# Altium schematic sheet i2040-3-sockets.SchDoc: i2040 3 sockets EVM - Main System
size 431 x 279 mm; VersionControl_RevNumber: 1; Date: Not shown in title block; ApprovedBy: Not shown in title block; CheckedBy: Not shown in title block; Author: Not shown in title block; CompanyName: Texas Instruments; DrawnBy: Mars Leung; Engineer: Mars Leung; Organization: Smartgrid Hong Kong; Address1: Not shown in title block; Address2: Not shown in title block; Address3: Not shown in title block; Address4: Not shown in title block; DocumentNumber: 1; Revision: Use project parameter SCH_Rev; SheetNumber: 1; SheetTotal: 3; PageSetup: Record=PageOptions|CenterHorizontal=True|CenterVertical=True|PrintScale=0.62|XCorrection=1.00|YCorrection=1.00|PrintKind=0|BorderSize=5000000|LeftOffset=0|BottomOffset=0|Orientation=2|PaperLength=1000|PaperWidth=1000|Scale=100|PaperSource=15|PrintQuality=600|MediaType=1|DitherType=10|PaperKind=Letter|PrintScaleMode=1
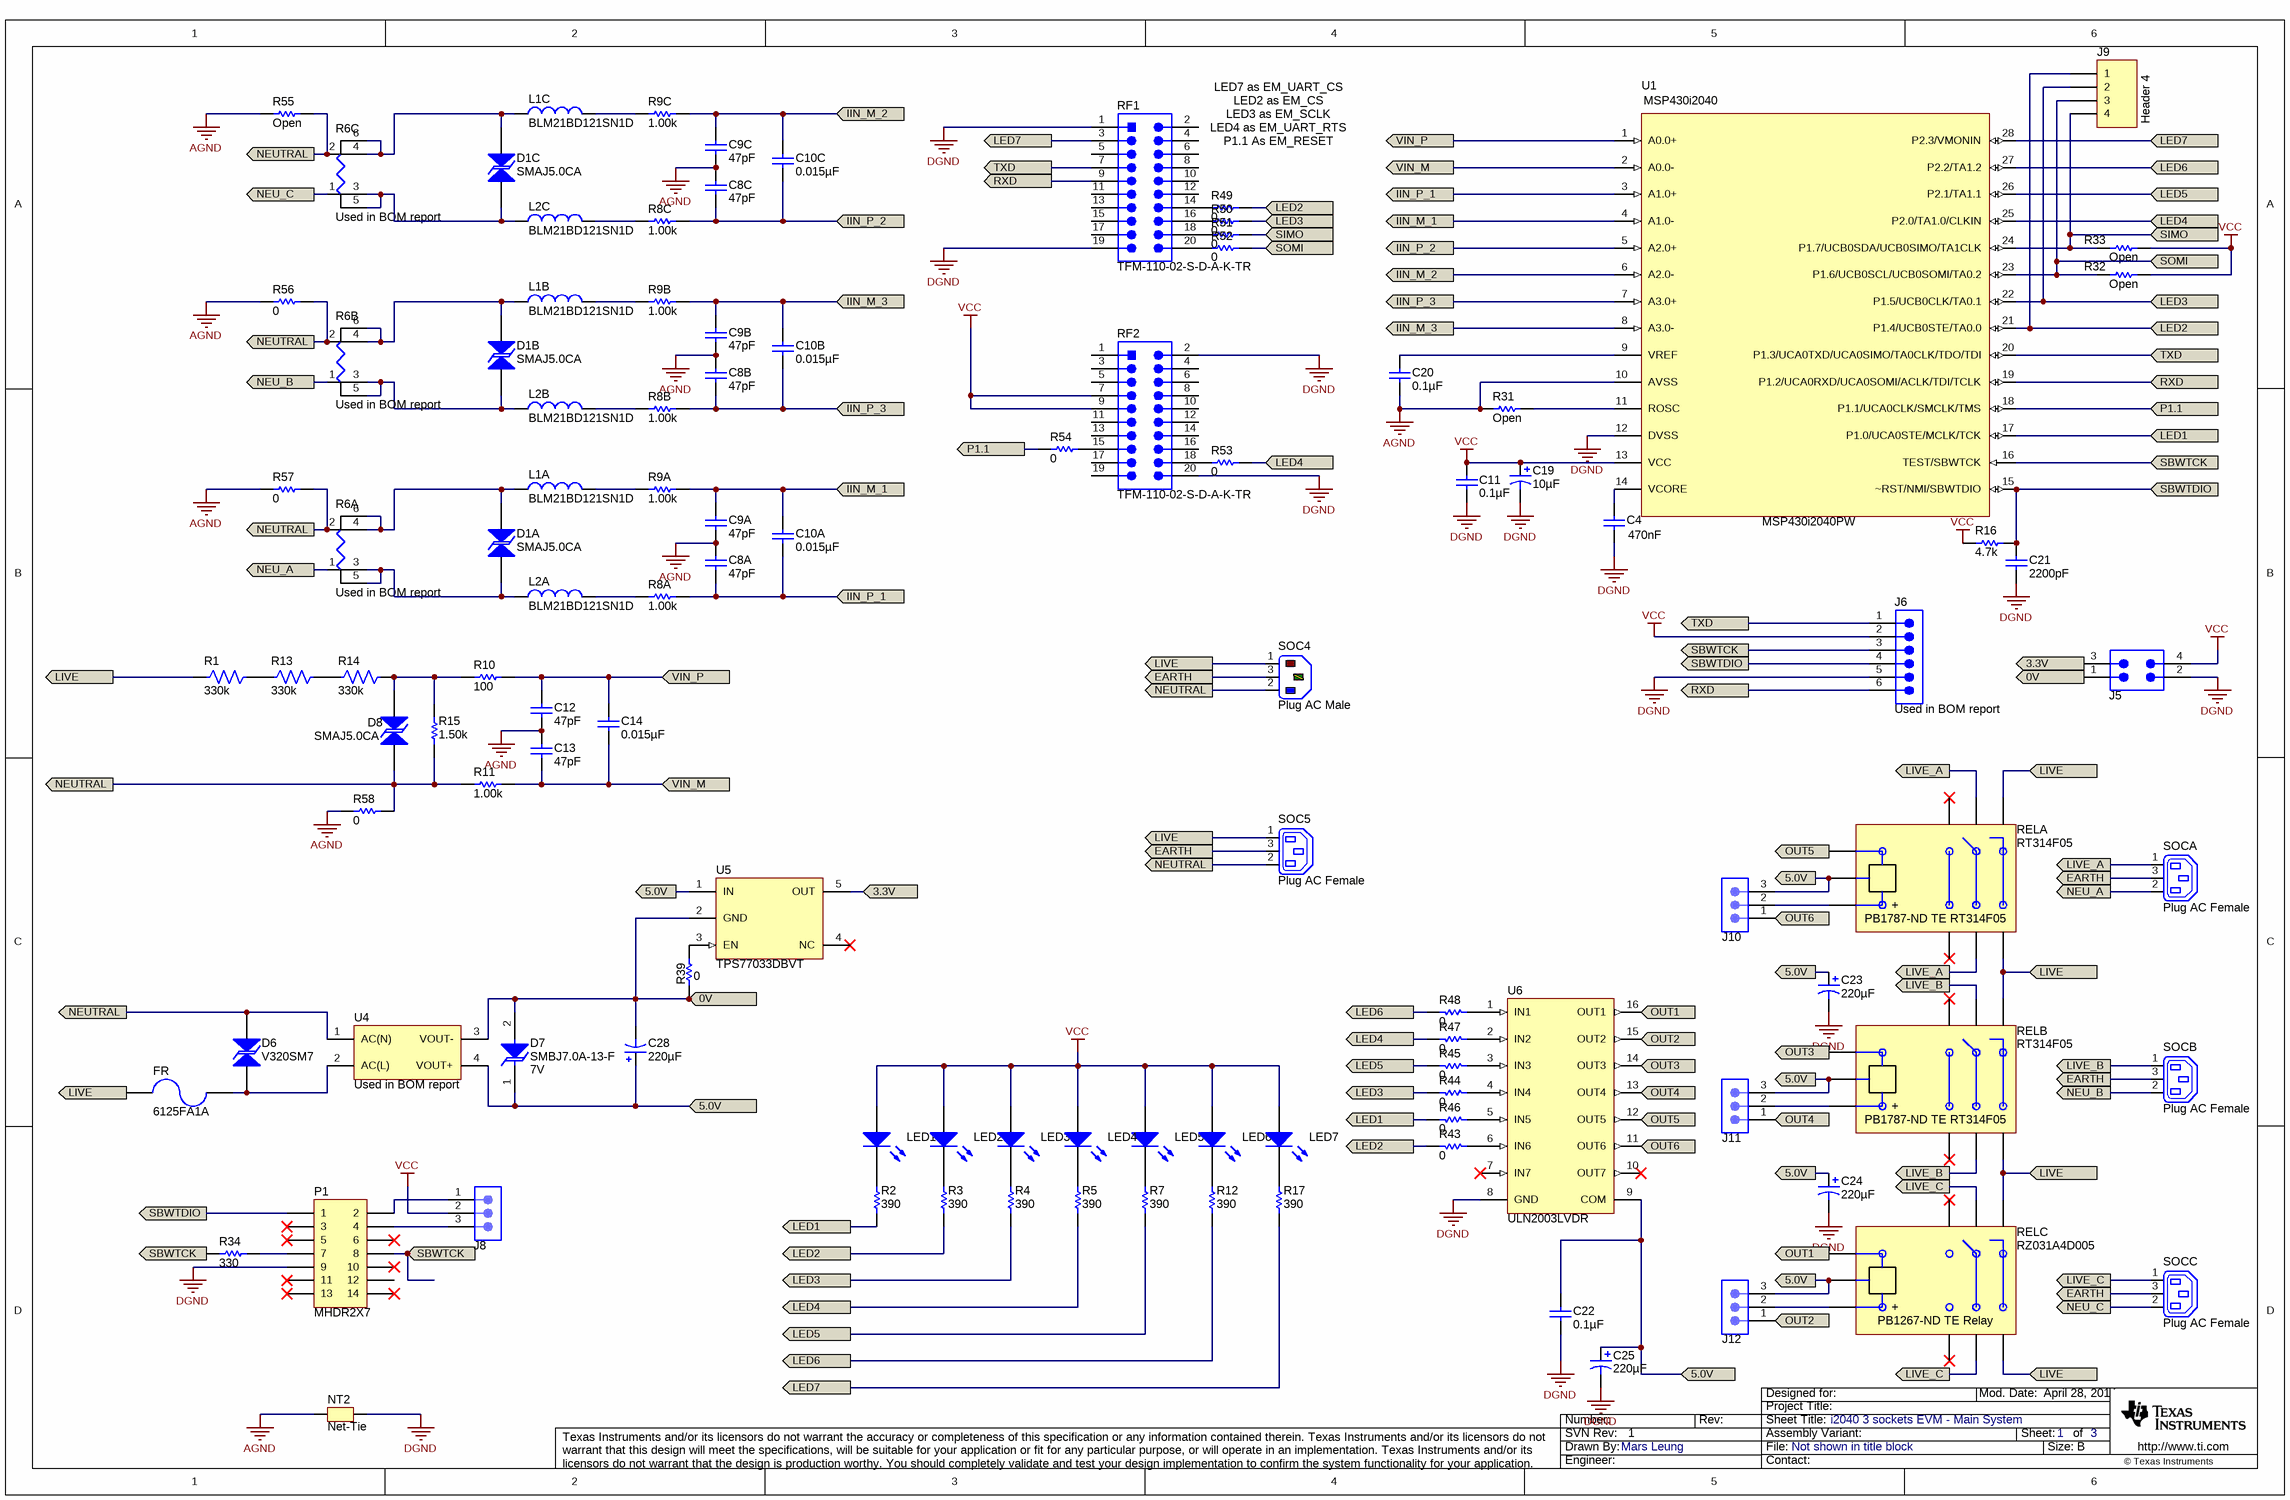
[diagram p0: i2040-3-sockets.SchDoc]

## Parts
C4  470nF  [0603]
C8A  ValueDisplayed: 47pF  [0603]  (hidden comment: 06035A470JAT2A)
C8B  ValueDisplayed: 47pF  [0603]  (hidden comment: 06035A470JAT2A)
C8C  ValueDisplayed: 47pF  [0603]  (hidden comment: 06035A470JAT2A)
C9A  ValueDisplayed: 47pF  [0603]  (hidden comment: 06035A470JAT2A)
C9B  ValueDisplayed: 47pF  [0603]  (hidden comment: 06035A470JAT2A)
C9C  ValueDisplayed: 47pF  [0603]  (hidden comment: 06035A470JAT2A)
C10A  ValueDisplayed: 0.015µF  [0603]  (hidden comment: GRM188R71C153KA01D)
C10B  ValueDisplayed: 0.015µF  [0603]  (hidden comment: GRM188R71C153KA01D)
C10C  ValueDisplayed: 0.015µF  [0603]  (hidden comment: GRM188R71C153KA01D)
C11  ValueDisplayed: 0.1µF  [0402]  (hidden comment: 0.1uF)
C12  ValueDisplayed: 47pF  [0603]  (hidden comment: 06035A470JAT2A)
C13  ValueDisplayed: 47pF  [0603]  (hidden comment: 06035A470JAT2A)
C14  ValueDisplayed: 0.015µF  [0603]  (hidden comment: GRM188R71C153KA01D)
C19  ValueDisplayed: 10µF  [3528-21]  (hidden comment: 293D106X0010B2TE3)
C20  ValueDisplayed: 0.1µF  [0402]  (hidden comment: 0.1uF)
C21  ValueDisplayed: 2200pF  [0603]  (hidden comment: C0603X222K5RACTU)
C22  ValueDisplayed: 0.1µF  [0402]  (hidden comment: 0.1uF)
C23  ValueDisplayed: 220µF  [7343-31]  (hidden comment: 293D227X96R3D2TE3)
C24  ValueDisplayed: 220µF  [7343-31]  (hidden comment: 293D227X96R3D2TE3)
C25  ValueDisplayed: 220µF  [7343-31]  (hidden comment: 293D227X96R3D2TE3)
C28  ValueDisplayed: 220µF  [7343-31]  (hidden comment: 293D227X96R3D2TE3)
D1A  SMAJ5.0CA  [DSO-C2/X1.8]
D1B  SMAJ5.0CA  [DSO-C2/X1.8]
D1C  SMAJ5.0CA  [DSO-C2/X1.8]
D6  V320SM7  [V320SM7]
D7  SMBJ7.0A-13-F  value 7V  [SMB]
D8  SMAJ5.0CA  [DSO-C2/X1.8]
FR  6125FA1A  [6125FA]
J5  TSW-102-07-G-D  [TSW-102-07-G-D]  (value not drawn)
J6  Used in BOM report  [6-pin header (1.27mm)]
J8  PBC03SAAN  [PBC03SAAN]  (value not drawn)
J9  Header 4  [HDR1X4]
J10  PBC03SAAN  [PBC03SAAN]  (value not drawn)
J11  PBC03SAAN  [PBC03SAAN]  (value not drawn)
J12  PBC03SAAN  [PBC03SAAN]  (value not drawn)
L1A  BLM21BD121SN1D  [YW0805]
L1B  BLM21BD121SN1D  [YW0805]
L1C  BLM21BD121SN1D  [YW0805]
L2A  BLM21BD121SN1D  [YW0805]
L2B  BLM21BD121SN1D  [YW0805]
L2C  BLM21BD121SN1D  [YW0805]
LED1  Used in BOM report  [0805-LED]  (value not drawn)
LED2  Used in BOM report  [0805-LED]  (value not drawn)
LED3  Used in BOM report  [0805-LED]  (value not drawn)
LED4  Used in BOM report  [0805-LED]  (value not drawn)
LED5  Used in BOM report  [0805-LED]  (value not drawn)
LED6  Used in BOM report  [0805-LED]  (value not drawn)
LED7  Used in BOM report  [0805-LED]  (value not drawn)
NT2  Net-Tie  [Net-Tie_10mil]  (net tie, no BOM)
P1  MHDR2X7  [2X7BOXHEADER]
R1  330k  [R2512]
R2  390  [0603]
R3  390  [0603]
R4  390  [0603]
R5  390  [0603]
R6A  Used in BOM report  [Current Sensing Pad]
R6B  Used in BOM report  [Current Sensing Pad]
R6C  Used in BOM report  [Current Sensing Pad]
R7  390  [0603]
R8A  1.00k  [0603]
R8B  1.00k  [0603]
R8C  1.00k  [0603]
R9A  1.00k  [0603]
R9B  1.00k  [0603]
R9C  1.00k  [0603]
R10  100  [0603]
R11  1.00k  [0603]
R12  390  [0603]
R13  330k  [R2512]
R14  330k  [R2512]
R15  1.50k  [0805]
R16  4.7k  [0603]
R17  390  [0603]
R31  Open  [0603]
R32  Open  [0603]
R33  Open  [0603]
R34  330  [0603]
R39  0  [0603]
R43  0  [0603]
R44  0  [0603]
R45  0  [0603]
R46  0  [0603]
R47  0  [0603]
R48  0  [0603]
R49  0  [0603]
R50  0  [0603]
R51  0  [0603]
R52  0  [0603]
R53  0  [0603]
R54  0  [0603]
R55  value Open  [0805_HV]  (hidden comment: CRCW08050000Z0EA)
R56  value 0  [0805_HV]  (hidden comment: CRCW08050000Z0EA)
R57  value 0  [0805_HV]  (hidden comment: CRCW08050000Z0EA)
R58  value 0  [0805_HV]  (hidden comment: CRCW08050000Z0EA)
RELA  RT314F05  [TE RELAY TYPE A]
RELB  RT314F05  [TE RELAY TYPE A]
RELC  RZ031A4D005  [TE RELAY TYPE A]
RF1  TFM-110-02-S-D-A-K-TR  [Samtec_TFM-110-02-S-D-A-K]
RF2  TFM-110-02-S-D-A-K-TR  [Samtec_TFM-110-02-S-D-A-K]
SOC4  Plug AC Male  [IEC9.14-2H3]
SOC5  Plug AC Female  [IEC7-2H3]
SOCA  Plug AC Female  [IEC7-2H3]
SOCB  Plug AC Female  [IEC7-2H3]
SOCC  Plug AC Female  [IEC7-2H3]
U1  MSP430i2040PW  [TSSO10x6-G28]
U4  Used in BOM report  [VSK-S1]
U5  TPS77033DBVT  [DBV0005A_N]
U6  ULN2003LVDR  [D0016A_N]

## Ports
0V, 3.3V, 5.0V, EARTH, IIN_M_1, IIN_M_2, IIN_M_3, IIN_P_1, IIN_P_2, IIN_P_3, LED1, LED2, LED3, LED4, LED5, LED6, LED7, LIVE, LIVE_A, LIVE_B, LIVE_C, NEU_A, NEU_B, NEU_C, NEUTRAL, OUT1, OUT2, OUT3, OUT4, OUT5, OUT6, P1.1, RXD, SBWTCK, SBWTDIO, SIMO, SOMI, TXD, VIN_M, VIN_P

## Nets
AGND: C8A.1 C8B.1 C8C.1 C9A.2 C9B.2 C9C.2 C12.2 C13.1 C20.2 NT2.1 R31.1 R55.1 R56.1 R57.1 R58.1 U1.10(AVSS)
DGND: C4.2 C11.2 C19.2(-) C21.2 C22.2 C23.2(-) C24.2(-) C25.2(-) J5.2 J6.5 NT2.2 P1.9 RF1.1 RF1.19 RF2.2 RF2.20 U1.12(DVSS) U6.8(GND)
VCC: C11.1 C19.1(+) J5.4 J6.2 J8.2 LED1.1(A) LED2.1(A) LED3.1(A) LED4.1(A) LED5.1(A) LED6.1(A) LED7.1(A) R16.1 R32.2 R33.2 RF2.7 RF2.9 U1.13(VCC)
0V: C28.2(-) D7.2(A) J5.1 R39.2 U4.3(VOUT-) U5.2(GND) ; port 0V
3.3V: J5.3 U5.5(OUT) ; port 3.3V
5.0V: C22.1 C23.1(+) C24.1(+) C25.1(+) C28.1(+) D7.1(K) J10.3 J11.3 J12.3 RELA.9 RELB.9 RELC.9 U4.4(VOUT+) U5.1(IN) U6.9(COM) ; port 5.0V
EARTH: SOC4.3(E) SOC5.3(E) SOCA.3(E) SOCB.3(E) SOCC.3(E) ; port EARTH
IIN_M_1: C9A.1 C10A.1 R9A.2 U1.4(A1.0-) ; port IIN_M_1
IIN_M_2: C9C.1 C10C.1 R9C.2 U1.6(A2.0-) ; port IIN_M_2
IIN_M_3: C9B.1 C10B.1 R9B.2 U1.8(A3.0-) ; port IIN_M_3
IIN_P_1: C8A.2 C10A.2 R8A.2 U1.3(A1.0+) ; port IIN_P_1
IIN_P_2: C8C.2 C10C.2 R8C.2 U1.5(A2.0+) ; port IIN_P_2
IIN_P_3: C8B.2 C10B.2 R8B.2 U1.7(A3.0+) ; port IIN_P_3
LED1: R2.1 R46.1 U1.17(P1.0/UCA0STE/MCLK/TCK) ; port LED1
LED2: J9.1 R3.1 R43.1 R49.2 U1.21(P1.4/UCB0STE/TA0.0) ; port LED2
LED3: J9.2 R4.1 R44.1 R50.2 U1.22(P1.5/UCB0CLK/TA0.1) ; port LED3
LED4: R5.1 R47.1 R53.2 U1.25(P2.0/TA1.0/CLKIN) ; port LED4
LED5: R7.1 R45.1 U1.26(P2.1/TA1.1) ; port LED5
LED6: R12.1 R48.1 U1.27(P2.2/TA1.2) ; port LED6
LED7: R17.1 RF1.3 U1.28(P2.3/VMONIN) ; port LED7
LIVE: FR.2 R1.1 RELA.7 RELA.8 RELB.7 RELB.8 RELC.7 RELC.8 SOC4.1(L) SOC5.1(L) ; port LIVE
LIVE_A: RELA.5 RELA.6 SOCA.1(L) ; port LIVE_A
LIVE_B: RELB.5 RELB.6 SOCB.1(L) ; port LIVE_B
LIVE_C: RELC.5 RELC.6 SOCC.1(L) ; port LIVE_C
NEU_A: R6A.1 SOCA.2(N) ; port NEU_A
NEU_B: R6B.1 SOCB.2(N) ; port NEU_B
NEU_C: R6C.1 SOCC.2(N) ; port NEU_C
NEUTRAL: D6.2 D8.1 R6A.2 R6B.2 R6C.2 R11.1 R15.1 R55.2 R56.2 R57.2 R58.2 SOC4.2(N) SOC5.2(N) U4.1(AC(N)) ; port NEUTRAL
OUT1: RELC.1 U6.16(OUT1) ; port OUT1
OUT2: J12.1 U6.15(OUT2) ; port OUT2
OUT3: RELB.1 U6.14(OUT3) ; port OUT3
OUT4: J11.1 U6.13(OUT4) ; port OUT4
OUT5: RELA.1 U6.12(OUT5) ; port OUT5
OUT6: J10.1 U6.11(OUT6) ; port OUT6
P1.1: R54.1 U1.18(P1.1/UCA0CLK/SMCLK/TMS) ; port P1.1
RXD: J6.6 RF1.9 U1.19(P1.2/UCA0RXD/UCA0SOMI/ACLK/TDI/TCLK) ; port RXD
SBWTCK: J6.3 P1.8 R34.1 U1.16(TEST/SBWTCK) ; port SBWTCK
SBWTDIO: C21.1 J6.4 P1.1 R16.2 U1.15(~RST/NMI/SBWTDIO) ; port SBWTDIO
SIMO: J9.4 R33.1 R51.2 U1.24(P1.7/UCB0SDA/UCB0SIMO/TA1CLK) ; port SIMO
SOMI: J9.3 R32.1 R52.2 U1.23(P1.6/UCB0SCL/UCB0SOMI/TA0.2) ; port SOMI
TXD: J6.1 RF1.7 U1.20(P1.3/UCA0TXD/UCA0SIMO/TA0CLK/TDO/TDI) ; port TXD
VIN_M: C13.2 C14.2 R11.2 U1.2(A0.0-) ; port VIN_M
VIN_P: C12.1 C14.1 R10.2 U1.1(A0.0+) ; port VIN_P
NetC4_1: C4.1 U1.14(VCORE)
NetC20_1: C20.1 U1.9(VREF)
NetD1A_1: D1A.1 L2A.1 R6A.3 R6A.5
NetD1A_2: D1A.2 L1A.1 R6A.4 R6A.6
NetD1B_1: D1B.1 L2B.1 R6B.3 R6B.5
NetD1B_2: D1B.2 L1B.1 R6B.4 R6B.6
NetD1C_1: D1C.1 L2C.1 R6C.3 R6C.5
NetD1C_2: D1C.2 L1C.1 R6C.4 R6C.6
NetD6_1: D6.1 FR.1 U4.2(AC(L))
NetD8_2: D8.2 R10.1 R14.2 R15.2
NetJ8_1: J8.1 P1.2
NetJ8_3: J8.3 P1.4
NetJ10_2: J10.2 RELA.2
NetJ11_2: J11.2 RELB.2
NetJ12_2: J12.2 RELC.2(A1)
NetL1A_2: L1A.2 R9A.1
NetL1B_2: L1B.2 R9B.1
NetL1C_2: L1C.2 R9C.1
NetL2A_2: L2A.2 R8A.1
NetL2B_2: L2B.2 R8B.1
NetL2C_2: L2C.2 R8C.1
NetLED1_2: LED1.2(K) R2.2
NetLED2_2: LED2.2(K) R3.2
NetLED3_2: LED3.2(K) R4.2
NetLED4_2: LED4.2(K) R5.2
NetLED5_2: LED5.2(K) R7.2
NetLED6_2: LED6.2(K) R12.2
NetLED7_2: LED7.2(K) R17.2
NetP1_7: P1.7 R34.2
NetR1_2: R1.2 R13.1
NetR13_2: R13.2 R14.1
NetR31_2: R31.2 U1.11(ROSC)
NetR39_1: R39.1 U5.3(EN)
NetR43_2: R43.2 U6.6(IN6)
NetR44_2: R44.2 U6.4(IN4)
NetR45_2: R45.2 U6.3(IN3)
NetR46_2: R46.2 U6.5(IN5)
NetR47_2: R47.2 U6.2(IN2)
NetR48_2: R48.2 U6.1(IN1)
NetR49_1: R49.1 RF1.14
NetR50_1: R50.1 RF1.16
NetR51_1: R51.1 RF1.18
NetR52_1: R52.1 RF1.20
NetR53_1: R53.1 RF2.18
NetR54_2: R54.2 RF2.15

Not connected (* = marked no-connect by the designer): P1 3* 5* 6* 10* 11* 12 13* 14*; RELA 3* 4*; RELB 3* 4*; RELC 3* 4*; RF1 2 4 5 6 8 10 11 12 13 15 17; RF2 1 3 4 5 6 8 10 11 12 13 14 16 17 19; U5 4(NC)*; U6 7(IN7)* 10(OUT7)*

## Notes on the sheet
- LED7 as EM_UART_CS
- LED2 as EM_CS
- LED3 as EM_SCLK
- LED4 as EM_UART_RTS
- P1.1 As EM_RESET

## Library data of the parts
C4 = Capacitor: CAP, CERM, 470nF, 16V, [TempCo], xx%, [PackageReference]; Manufacturer: Used in BOM report; PartNumber: EMK107F474ZA-T; Polarized: N; U/M: EA
C8A C8B C8C C9A C9B C9C C12 C13 = 06035A470JAT2A: CAP, CERM, 47pF, 50V, +/-5%, C0G/NP0, 0603; Manufacturer: AVX; Polarized: N; CompType: Capacitor; U/M: EA; Cap_F: 0.000000000047; Tolerance_%: 5; ESR_Ohm: 0.174; Value1: 0.174 ohm; VDC_V: 50; TaMin_C: -55; TaMax_C: 125
C10A C10B C10C C14 = GRM188R71C153KA01D: CAP, CERM, 0.015uF, 16V, +/-10%, X7R, 0603; Manufacturer: MuRata; Polarized: N; CompType: Capacitor; U/M: EA; Cap_F: 0.000000015; Tolerance_%: 10; Value1: Unknown; VDC_V: 16; TaMin_C: -55; TaMax_C: 125
C11 C20 C22 = C1005X5R1A104K: CAP, CERM, 0.1uF, 10V, +/-10%, X5R, 0402; Manufacturer: TDK; Polarized: N; CompType: Capacitor; U/M: EA; Cap_F: 0.0000001; Tolerance_%: 10; ESR_Ohm: 0.0186; Value1: 0.0186 ohm; TaMin_C: -55; TaMax_C: 85
C19 = 293D106X0010B2TE3: CAP, TANT, 10uF, 10V, +/-20%, 2.5 ohm, 3528-21 SMD; Manufacturer: Vishay-Sprague; Polarized: Y; CompType: Capacitor; U/M: EA; Cap_F: 0.00001; Tolerance_%: 20; Value1: 2.5 ohm; VDC_V: 10; ESR_Ohm: 2.5; IRMS_A: 0.18; TaMin_C: -55; TaMax_C: 125; Cap_Case: B
C21 = C0603X222K5RACTU: CAP, CERM, 2200pF, 50V, +/-10%, X7R, 0603; Manufacturer: Kemet; Polarized: N; CompType: Capacitor; U/M: EA; Cap_F: 0.0000000022; Tolerance_%: 10; Value1: Unknown; VDC_V: 50; TaMin_C: -55; TaMax_C: 125
C23-C25 C28 = 293D227X96R3D2TE3: CAP, TANT, 220uF, 6.3V, +/-10%, 0.6 ohm, 7343-31 SMD; Manufacturer: Vishay-Sprague; Polarized: Y; CompType: Capacitor; U/M: EA; Cap_F: 0.00022; Tolerance_%: 10; Value1: 0.6 ohm; VDC_V: 6.3; ESR_Ohm: 0.6; IRMS_A: 0.5; TaMin_C: -55; TaMax_C: 125; Cap_Case: D
D1A D1B D1C D8 = SMAJ5.0CA: Manufacturer: Littelfuse Inc; SymbolVersion: use current date i.e. 2008-05-20; SymbolCreator: Use LDAP id; CompType: Used in some BOM reports.  Useful for finding later.; U/M: EA, IN, or GM
D6 = V320SM7: Manufacturer: Littelfuse Inc; SymbolVersion: use current date i.e. 2008-05-20; SymbolCreator: Use LDAP id; CompType: Used in some BOM reports.  Useful for finding later.; U/M: EA, IN, or GM
D7 = SMBJ7.0A-13-F: Diode, TVS, Uni, 7V, 600W, SMB; Manufacturer: Diodes Inc.; U/M: EA; Power_W: 5; Vr_V: 7; Value1: 5W
FR = 6125FA1A: Fuse, 1A,125V, SMD; Manufacturer: Cooper Bussman; Alternate Manufacturer: Any; Alternate PartNumber: Equivalent; U/M: EA; OpeningTime_100%_min: 4; OpeningTime_200%_max: 5; VDC_V: 125; Interrupt_DC: 300; Interrupt_AC: 50; Irating_A: 1; Rtyp_Ohm: 0.11; MeltingTyp: 0.14; Vdrop: 0.17; Soldering_Wave_MaxTemp_C: 260; Soldering_Wave_MaxTime_s: 10; Soldering_Reflow_MaxTime_s: 30
J5 = TSW-102-07-G-D: Header, TH, 100mil, 2x2, Gold plated, 230 mil above insulator; Manufacturer: Samtec, Inc.; Alternate Manufacturer: Any; Alternate PartNumber: Equivalent; U/M: EA
J6 = 6 pin header (1.27mm): SymbolVersion: use current date i.e. 2008-05-20; SymbolCreator: Use LDAP id; CompType: Used in some BOM reports.  Useful for finding later.; U/M: EA, IN, or GM
J8 J10-J12 = PBC03SAAN: Header, TH, 100mil, 1x3, Gold plated, 230 mil above insulator; Manufacturer: Sullins Connector Solutions; Alternate Manufacturer: Any; Alternate PartNumber: Equivalent; U/M: EA
J9 = Header 4: Header, 4-Pin
L1A L1B L1C L2A L2B L2C = Inductor: Inductor, FERRITE CHIP 120 OHM 0805; Manufacturer: Murata Electronics; U/M: EA
LED1 LED5 = LED-0805: Red; SymbolVersion: use current date i.e. 2008-05-20; SymbolCreator: Use LDAP id; CompType: Used in some BOM reports.  Useful for finding later.; U/M: EA, IN, or GM
LED2 LED6 = LED-0805: Green; SymbolVersion: use current date i.e. 2008-05-20; SymbolCreator: Use LDAP id; CompType: Used in some BOM reports.  Useful for finding later.; U/M: EA, IN, or GM
LED3 LED7 = LED-0805: Blue; SymbolVersion: use current date i.e. 2008-05-20; SymbolCreator: Use LDAP id; CompType: Used in some BOM reports.  Useful for finding later.; U/M: EA, IN, or GM
LED4 = LED-0805: White; SymbolVersion: use current date i.e. 2008-05-20; SymbolCreator: Use LDAP id; CompType: Used in some BOM reports.  Useful for finding later.; U/M: EA, IN, or GM
NT2 = Net-Tie: Single point connection between nets.; SymbolCreator: codlsc
P1 = MHDR2X7: Header, 7-Pin, Dual row
R1 R13 R14 = R2512: Resistor, 330kOhm, 1W, 1%; Manufacturer: Vishay Dale; PartNumber: CRCW2512330KFKEG; Area: 35100
R2-R5 R7 R12 R17 = RC0603JR-07390RL: RES, 390 ohm, 5%, 0.1W, 0603; Manufacturer: Yageo America; CompType: Resistor; Value_Code: 390R; Tolerance_%: 5; Power_W: 0.1; VDC_V: 50; TempCo: 100 ppm/C; EIA_Code: E24; U/M: EA
R6A R6B R6C = ULRB12512R0005FLFSLT: Shunt Resistor; SymbolVersion: use current date i.e. 2008-05-20; SymbolCreator: Use LDAP id; CompType: Used in some BOM reports.  Useful for finding later.; U/M: EA, IN, or GM
R8A R8B R8C R9A R9B R9C R11 = CRCW06031K00FKEA: RES, 1.00k ohm, 1%, 0.1W, 0603; Manufacturer: Vishay-Dale; CompType: Resistor; Res_ohm: 1000; Value_Code: 1k00; Tolerance_%: 1; Power_W: 0.1; VDC_V: 75; TempCo: 100 ppm/C; EIA_Code: E96; U/M: EA
R10 = CRCW0603100RFKEA: RES, 100 ohm, 1%, 0.1W, 0603; Manufacturer: Vishay-Dale; CompType: Resistor; Value_Code: 100R; Tolerance_%: 1; Power_W: 0.1; VDC_V: 75; TempCo: 100 ppm/C; EIA_Code: E96; U/M: EA
R15 = CRCW08051K50FKEA: RES, 1.50k ohm, 1%, 0.125W, 0805; Manufacturer: Vishay-Dale; CompType: Resistor; Res_ohm: 1500; Value_Code: 1k50; Tolerance_%: 1; Power_W: 0.125; VDC_V: 150; TempCo: 100 ppm/C; EIA_Code: E96; U/M: EA
R16 = CRCW06034K70JNEA: RES, 4.7k ohm, 5%, 0.1W, 0603; Manufacturer: Vishay-Dale; CompType: Resistor; Res_ohm: 4700; Value_Code: 4k70; Tolerance_%: 5; Power_W: 0.1; VDC_V: 75; TempCo: 200 ppm/C; EIA_Code: E24; U/M: EA
R31 = Resistor: RES, Open ohm, x%, xW, 0603; Manufacturer: Used in BOM report; U/M: EA
R32 R33 = Resistor: RES, xxx ohm, x%, xW, [PackageReference]; Manufacturer: Used in BOM report; U/M: EA
R34 = CRCW0603330RJNEA: RES, 330 ohm, 5%, 0.1W, 0603; Manufacturer: Vishay-Dale; CompType: Resistor; U/M: EA; Value_Code: 330R; Tolerance_%: 5; Power_W: 0.1; VDC_V: 75; TempCo: 200 ppm/C; EIA_Code: E24
R39 R43-R54 = CRCW06030000Z0EA: RES, 0 ohm, 5%, 0.1W, 0603; Manufacturer: Vishay-Dale; CompType: Resistor; Value_Code: 0000; Tolerance_%: 5; Power_W: 0.1; VDC_V: 75; TempCo: 200 ppm/C; EIA_Code: E24; U/M: EA
R55 = CRCW08050000Z0EA: RES, 0 ohm, 5%, 0.125W, 0805; Manufacturer: Vishay-Dale; CompType: Resistor; Res_ohm: 0; Value_Code: 0000; Tolerance_%: 5; Power_W: 0.125; VDC_V: 150; TempCo: 200 ppm/C; EIA_Code: E24; U/M: EA
R56-R58 = CRCW08050000Z0EA: RES, 0 ohm, 5%, 0.125W, 0805; Manufacturer: Vishay-Dale; CompType: Resistor; Value_Code: 0000; Tolerance_%: 5; Power_W: 0.125; VDC_V: 150; TempCo: 200 ppm/C; EIA_Code: E24; U/M: EA
RELA RELB = RT314F05: General Purpose Relays 5V 16A 1CO THT POWER RELAY; Manufacturer: TE Electronics; SymbolVersion: use current date i.e. 2008-05-20; SymbolCreator: Use a-id; CompType: Used in some BOM reports.  Useful for finding later.; U/M: EA, IN, or GM; Coil Type: Bistable; Contact Form: 1 Form C (SPDT-BM); Contact Termination: Pin; Power Consumption: 600 mW; Brand: TE Connectivity / Schrack; Coil Resistance: 42 Ohms; Switching Voltage: 400 VAC
RELC = RZ03-1A4-D005: RELAY GEN PURPOSE SPST 16A 5V; Manufacturer: TE Electronics; SymbolVersion: use current date i.e. 2008-05-20; SymbolCreator: Use a-id; CompType: Used in some BOM reports.  Useful for finding later.; U/M: EA, IN, or GM; Relay Type: General Purpose; Coil Type: Non Latching; Coil Current: 84mA; Coil Voltage: 5VDC; Contact Form: SPST-NO (1 Form A); Switching Voltage: 400VAC - Max; Turn On Voltage (Max): 3.5 VDC; Turn Off Voltage (Min): 0.5 VDC; Operate Time: 8ms; Release Time: 6ms; Coil Power: 420 mW; Coil Resistance: 60 Ohms
RF1 RF2 = TFM-110-02-S-D-A-K-TR: CONN SHRD HDR HDR 20 POS 1.27MM SLDR ST SMD; Manufacturer: Samtec; SymbolCreator: a0412235; CompType: Header; U/M: EA
SOC4 = Plug AC Male: IEC Mains Power Inlet, EN60 320-1 C14 Class I Cold Condition, PC Flange Rear Mount, Chassis Plug; PackageDocument: ver.80, 15-Sep-2003; MaximumRating: 10A, 250V a.c. (UL & CSA 15A, 250V a.c.); MountingFixtures: Not drawn on schematic symbol.; PCB_Layout: Complies with manufacturer's recommendation.; DrillSize: Corresponds to nominal value.; Note: IEC Color Scheme employed for L, N and E.
SOC5 SOCA SOCB SOCC = Plug AC Female: IEC Mains Power Outlet, EN60 320-2-2 F Class I, PC Flange Rear Mount, Chassis Socket; PackageDocument: ver.80, 15-Sep-2003; MaximumRating: 10A, 250V a.c. (UL & CSA 15A, 250V a.c.); MountingFixtures: Not drawn on schematic symbol.; PCB_Layout: Complies with manufacturer's recommendation.; DrillSize: Corresponds to nominal value.
U1 = MSP430i2040: Manufacturer: Texas Instruments; SymbolVersion: use current date i.e. 2008-05-20; SymbolCreator: Use LDAP id; CompType: Used in some BOM reports.  Useful for finding later.; U/M: EA, IN, or GM
U4 = VSK-S2-5U: POWER SUPPLY SWITCHING 5V 2W; SymbolVersion: use current date i.e. 2008-05-20; SymbolCreator: Use a-id; CompType: Used in some BOM reports.  Useful for finding later.; U/M: EA, IN, or GM; Number of Outputs: 1; Voltage - Input: 85 ~ 305 VAC; Current - Output (Max): 400mA; Power Supply Type: Switching (Closed Frame); Efficiency: 70%; Line Regulation: ±2%; Load Regulation: ±5%; Approvals: CE, cULus
U5 = TPS76133DBVR: LOW-POWER 50-mA 3.3 V LDO LINEAR REGULATORS, DBV0005A; Alternate Manufacturer: None; Manufacturer: Texas Instruments; SymbolCreator: a0799628; CompType: IC; U/M: EA
U6 = ULN2003LVD: 7-Channel Relay and Inductive Load Sink Driver, D0016A; Alternate Manufacturer: None; Manufacturer: Texas Instruments; SymbolCreator: a0411947; CompType: IC; U/M: EA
